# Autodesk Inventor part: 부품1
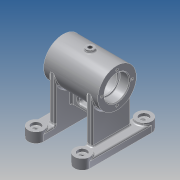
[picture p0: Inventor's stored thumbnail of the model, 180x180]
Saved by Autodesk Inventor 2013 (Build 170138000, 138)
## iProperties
Created: 2015-11
Part Number: 부품1
Material: 알루미늄 6061
Document SubType Name: Modeling
Designer: Administrator
Density: 2.71 g/cm^3
Mass: 358.625 g
Surface Area: 460.08 cm^2
Volume: 132.334 cm^3
Author: Administrator
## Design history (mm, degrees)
sketch "스케치1"
  geometry: L1 (0, 0)-(70, 0); L2 (70, 0)-(70, 25); L3 (70, 25)-(0, 25); L4 (0, 25)-(0, 0); L5 (0, 16)-(12, 16); L6 (12, 16)-(12, 14); L7 (12, 14)-(14, 14); L8 (14, 14)-(14, 21); L9 (14, 21)-(56, 21); L10 (56, 21)-(56, 14); L11 (56, 14)-(58, 14); L12 (58, 14)-(58, 16); L13 (58, 16)-(70, 16)
  constraints: 26 end point, 8 parallel, 3 perpendicular, 2 collinear, 2 point on line, 1 horizontal
  dimensions: "d0" = 70 distance of L2.end L3.end; "d2" = 50 diameter of L3 L1; "d3" = 42 diameter of L9 L1; "d4" = 32 diameter of L13 L1; "d5" = 32 diameter of L5 L1; "d6" = 12 distance of L5.start L5.end; "d7" = 12 distance of L12.end L13.end; "d8" = 28 diameter of L7 L1; "d9" = 28 diameter of L11 L1; "d10" = 42 distance of L8.end L9.end
revolve "회전1" sketch "스케치1" stored, may be unused: angle "d11" = 90 deg
node "작업 평면1"
sketch "스케치2"
  geometry: L1 (-70, 25)-(-70, -25) reference; L2 (0, 25)-(0, -25) reference; L3 (-70, 25)-(-70, -25) reference; L4 (0, -25)-(-70, -25) reference; L5 (0, 25)-(-70, 25) reference; L6 (5, 40)-(5, -40); L7 (-35, 25)-(-35, -25); L8 (-5, 40)-(-5, -40); L9 (-15, 40)-(-15, -40); L10 (-55, 40)-(-55, -40); L11 (-75, 40)-(-75, -40); A1 r 10 centre (-5, 40) between (5, 40) and (-15, 40); A2 r 10 centre (-5, -40) between (-15, -40) and (5, -40); A3 r 10 centre (-65, -40) between (-75, -40) and (-55, -40); A4 r 10 centre (-65, 40) between (-55, 40) and (-75, 40); 1 further point
  constraints: 12 end point, 8 point on circle, 6 symmetric about line, 4 centre point, 2 coincident, 2 midpoint, 2 parallel, 2 tangent, 1 perpendicular, 2 other
  dimensions: "d13" = 80 distance of L6.start L6.end; "d16" = 40 vertical distance of L6.end point (0, 0); "d18" = 40 distance between parallel lines of L7 L6; "d19" = 20 distance between parallel lines of L9 L6; "d20" = 10 distance between parallel lines of L8 L6
extrude "돌출1" join sketch "스케치2" distance "d21" = 10; taper "d22" = 0 deg
sketch "스케치3"
  geometry: L1 (55, 40)-(55, -40) reference; L2 (75, -40)-(75, 40) reference; C1 r 10 at (65, -40); C2 r 10 at (5, -40); A1 r 10 centre (5, -40) between (-5, -40) and (15, -40) reference; A2 r 10 centre (5, 40) between (15, 40) and (-5, 40) reference; A3 r 10 centre (65, 40) between (75, 40) and (55, 40) reference; A4 r 10 centre (65, -40) between (55, -40) and (75, -40) reference; 3 further points
  constraints: 4 coincident, 2 centre point, 2 concentric, 2 horizontal alignment, 4 other
extrude "돌출2" join sketch "스케치3" distance "d23" = 3; taper "d24" = 0 deg
sketch "스케치4"
  geometry: L1 (80, 0)-(80, -10) reference; L2 (80, -10)-(80, -13) reference; L3 (0, 0)-(80, 0) reference; L4 (0, 0)-(0, -10) reference; L5 (80, -10)-(0, -10) reference; L6 (0, -10)-(0, -13) reference; L7 (65, -68)-(65, -10); L8 (0, -10)-(80, -10) reference; L9 (15, -68)-(15, -10); L10 (65, -10)-(15, -10); C1 r 21 at (40, -68) reference; A1 r 25 centre (40, -68) between (65, -68) and (15, -68) reference; A2 r 25 centre (40, -68) between (65, -68) and (15, -68); 1 further point
  constraints: 6 end point, 4 point on circle, 2 point on line, 2 tangent, 1 centre point, 1 coincident, 1 collinear, 1 concentric, 1 parallel, 1 perpendicular
extrude "돌출3" join sketch "스케치4" distance "d25" = 8; taper "d26" = 0 deg
sketch "스케치5"
  geometry: L1 (80, -10)-(0, -10) reference; L2 (0, 0)-(0, -10) reference; L3 (0, -10)-(0, -13) reference; L4 (0, 0)-(80, 0) reference; L5 (80, 0)-(80, -10) reference; L6 (80, -10)-(0, -10) reference; L7 (80, -10)-(80, -13) reference; L8 (65, -68)-(65, -10); L9 (15, -68)-(15, -10); L10 (65, -10)-(15, -10); C1 r 21 at (40, -68) reference; A1 r 25 centre (40, -68) between (65, -68) and (15, -68) reference; A2 r 25 centre (40, -68) between (65, -68) and (15, -68) reference; A3 r 25 centre (40, -68) between (65, -68) and (15, -68); 1 further point
  constraints: 6 end point, 6 point on circle, 2 point on line, 2 tangent, 1 centre point, 1 coincident, 1 collinear, 1 parallel, 1 perpendicular
extrude "돌출4" join sketch "스케치5" distance "d27" = 8; taper "d28" = 0 deg
sketch "스케치6"
  geometry: L1 (0, 25)-(7, 25) reference; L2 (7, 25)-(7, 58) reference; L3 (7, 58)-(-5, 58) reference; L4 (-5, 58)-(-5, 68) reference; L5 (-5, 68)-(15, 68) reference; L6 (15, 68)-(15, 25) reference; L7 (15, 25)-(55, 25) reference; L8 (55, 25)-(55, 68) reference; L9 (55, 68)-(75, 68) reference; L10 (75, 68)-(75, 58) reference; L11 (75, 58)-(63, 58) reference; L12 (63, 58)-(63, 25) reference; L13 (63, 25)-(70, 25) reference; L14 (70, 25)-(70, 16) reference; L15 (70, 16)-(58, 16) reference; L16 (58, 16)-(58, 14) reference; L17 (58, 14)-(56, 14) reference; L18 (56, 14)-(56, 21) reference; L19 (56, 21)-(14, 21) reference; L20 (14, 21)-(14, 14) reference; L21 (14, 14)-(12, 14) reference; L22 (12, 14)-(12, 16) reference; L23 (12, 16)-(0, 16) reference; L24 (0, 16)-(0, 25) reference; L25 (70, -25)-(0, -25) reference; L26 (0, -25)-(0, -16) reference; L27 (0, -16)-(12, -16) reference; L28 (12, -16)-(12, -14) reference; L29 (12, -14)-(14, -14) reference; L30 (14, -14)-(14, -21) reference; L31 (14, -21)-(56, -21) reference; L32 (56, -21)-(56, -14) reference; L33 (56, -14)-(58, -14) reference; L34 (58, -14)-(58, -16) reference; L35 (58, -16)-(70, -16) reference; L36 (70, -16)-(70, -25) reference; L37 (15, 45)-(55, 45); 1 further point
  constraints: 2 end point, 2 point on line, 1 perpendicular
  dimensions: "d29" = 20 distance between parallel lines of L37 L7
feature "리브1" sketch "스케치6" dims "d30" = 1, "d31" = 8, "d32" = 0, "d33" = 0, "d34" = 1, "d35" = 1
sketch "스케치7"
  geometry: L1 (40, -20.322)-(0, -20.322) reference; L2 (28, -13.5)-(12, -13.5); L3 (28, -6.5)-(12, -6.5); L4 (40, 23)-(60, 23) reference; L5 (-15, -70)-(55, -70) reference; L6 (40, -20.322)-(0, -20.322); L7 (20, -20.322)-(20, -16.631); A1 r 3.5 centre (28, -10) between (28, -13.5) and (28, -6.5); A2 r 3.5 centre (12, -10) between (12, -6.5) and (12, -13.5); 1 further point
  constraints: 8 end point, 4 point on circle, 3 tangent, 2 centre point, 2 equal length, 1 horizontal alignment, 1 midpoint, 1 perpendicular
  dimensions: "d36" = 7 diameter of A1; "d38" = 23 dimension on A2 A1; "d39" = 7 diameter of A2; "d40" = 33 vertical distance of A1.centre L4.start; "d41" = 11.5 dimension on A1 L7
extrude "돌출5" cut sketch "스케치7" stored distance "d42" = 8; taper "d43" = 0 deg
node "작업 평면2"
sketch "스케치8"
  geometry: C1 r 5 at (35, 0); 1 further point
  constraints: 1 centre point, 1 horizontal alignment
  dimensions: "d45" = 35 distance of C1.centre point (0, 0); "d46" = 10 diameter of C1
extrude "돌출6" join sketch "스케치8" stored distance "d47" = 8; taper "d48" = 0 deg
fillet "모깎기1" dims "d49" = 3
fillet "모깎기2" dims "d50" = 2
fillet "모깎기3" dims "d51" = 2
sketch "스케치9"
  geometry: C1 r 25 at (0, 0) reference; 1 further point
  constraints: 1 vertical alignment
  dimensions: "d52" = 20 distance of C1.centre point (0, 20)
hole "구멍1" sketch "스케치9" at (0, 20) diameter "d53" = 3.242; stored, may be unused: countersink angle "d57" = 90 deg, drill point angle "d59" = 118 deg; dims "d54" = 8, "d55" = 4, "d56" = 2, "d58" = 10
sketch "스케치10"
  geometry: C1 r 16 at (0, 0) reference; 1 further point
  constraints: 1 vertical alignment
  dimensions: "d60" = 20 distance of C1.centre point (0, 20)
hole "구멍2" sketch "스케치10" at (0, 20) diameter "d61" = 3.242; stored, may be unused: countersink angle "d65" = 90 deg, drill point angle "d67" = 118 deg; dims "d62" = 8, "d63" = 4, "d64" = 2, "d66" = 10
node "작업 평면3"
sketch "스케치11"
  geometry: 2 further points
  constraints: 1 horizontal alignment, 1 other
  dimensions: "d74" = 35 distance of point (0, 0) point (35, 0)
feature "엠보싱1" sketch "스케치11" dims "d0" = 70, "d2" = 50, "d3" = 42, "d4" = 32, "d5" = 32, "d6" = 12, "d7" = 12, "d8" = 28, "d9" = 28, "d10" = 42, "d75" = 0.5, "d76" = 0
fillet "모깎기4" dims "d77" = 0.3
chamfer "모따기1" distance "d78" = 1; stored, may be unused: second distance "d79" = 2, angle "d80" = 45 deg
sketch "스케치12"
  geometry: C1 r 10 at (0, 0) reference; C2 r 10 at (0, 80) reference; C3 r 10 at (60, 80) reference; C4 r 10 at (60, 0) reference; 1 further point
hole "구멍3" sketch "스케치12" at (0, 0), (0, 80), (60, 0), (60, 80) diameter "d81" = 6; stored, may be unused: countersink angle "d85" = 90 deg, drill point angle "d87" = 118 deg; dims "d82" = 6, "d83" = 12, "d84" = 4, "d86" = 10
chamfer "모따기2" distance "d88" = 1; stored, may be unused: second distance "d89" = 2, angle "d90" = 45 deg
fillet "모깎기5" dims "d91" = 0.3
hole "구멍4" diameter "d94" = 5.188; stored, may be unused: countersink angle "d98" = 90 deg, drill point angle "d100" = 118 deg; dims "d92" = 10, "d93" = 10, "d95" = 6, "d96" = 12, "d97" = 4, "d99" = 24.5
fillet "모깎기6" dims "d101" = 2
node "솔리드1"
pattern_circular "원형 패턴1" dims angle "d69" = 360 deg
pattern_circular "원형 패턴2" dims angle "d72" = 360 deg
node "투영된 루프1"
node "투영된 루프2"
node "투영된 루프3"
node "투영된 루프4"
node "절단 모서리 투영1"
node "절단 모서리 투영2"
node "절단 모서리 투영3"
other parameters: "d12" = 68, "d44" = -96
